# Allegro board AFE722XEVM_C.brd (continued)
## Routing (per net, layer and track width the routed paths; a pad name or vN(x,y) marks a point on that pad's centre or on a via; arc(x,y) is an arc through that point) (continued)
ADCA_DATA_0N: length 48.7
  TOP w0.152: v1(84.79,10.85) 84.75,10.81 84.75,9.53 J14.44 ; v1(50.07,34.82) 50.06,34.82 48.69,36.19 U1.54
  BOTTOM w0.152: v1(50.07,34.82) 50.29,34.61 50.29,34.57 50.57,34.29 50.84,34.29 63.46,21.67 74.19,21.67 83.87,11.99 83.87,11.18 84.15,10.9 84.73,10.9 v1(84.79,10.85)
ADCA_DATA_0P: length 48.7
  TOP w0.152: U1.55 48.88,36.4 49.87,35.41 49.88,35.41 50.01,35.28 50.26,35.28 50.53,35.01 50.53,35 50.76,34.77 v1(50.77,34.77) ; J14.46 84.43,9.53 84.43,10.49 84.33,10.59 84.33,11.33 v1(84.35,11.38)
  BOTTOM w0.152: v1(50.77,34.77) 50.77,34.75 63.58,21.95 74.31,21.95 83.11,13.15 83.3,13.15 83.34,13.19 83.53,13.19 83.66,13.06 83.66,12.87 83.62,12.83 83.62,12.64 84.15,12.1 84.15,11.57 84.34,11.38 v1(84.35,11.38)
ADCA_DATA_1N: length 48.7
  TOP w0.152: v1(48.49,34.8) 48.49,34.96 47.96,35.49 U1.52 ; v1(83.21,10.87) 83.21,10.26 83.22,10.25 83.22,9.56 J14.50
  BOTTOM w0.152: v1(83.21,10.87) 83.16,10.92 82.58,10.92 82.3,11.2 82.3,11.66 73.99,19.96 69.78,19.96 69.47,20.28 69.47,20.4 69.31,20.55 68.7,20.55 68.55,20.4 68.55,20.28 68.24,19.96 67.39,19.96 67.08,20.28 67.08,20.4 66.93,20.55 66.32,20.55 66.16,20.4 66.16,20.28 65.85,19.96 63.42,19.96 49,34.39 48.97,34.39 48.57,34.8 v1(48.49,34.8)
ADCA_DATA_1P: length 48.7
  TOP w0.152: U1.53 48.17,35.67 48.59,35.26 48.68,35.26 48.97,34.97 v1(49.17,34.87) ; v1(82.78,11.4) 82.78,11.09 82.75,11.06 82.75,10.68 82.81,10.63 82.81,10.6 82.93,10.48 82.93,9.53 J14.52
  BOTTOM w0.152: v1(49.17,34.87) 49.17,34.63 49.18,34.63 49.18,34.61 63.54,20.24 65.73,20.24 65.88,20.4 65.88,20.51 66.2,20.83 67.04,20.83 67.36,20.51 67.36,20.4 67.51,20.24 68.12,20.24 68.27,20.4 68.27,20.51 68.59,20.83 69.43,20.83 69.75,20.51 69.75,20.4 69.9,20.24 74.11,20.24 81.77,12.58 81.96,12.58 81.98,12.6 82.16,12.6 82.3,12.47 82.3,12.28 82.28,12.26 82.28,12.07 82.6,11.75 82.6,11.59 82.78,11.42 v1(82.78,11.4)
ADCB_DATA_0N: length 48.7
  TOP w0.152: v1(73.19,11.29) 73.25,11.2 73.25,9.53 J14.70 ; U1.44 44.28,35.69 43.52,34.92 43.42,34.92 43,34.5 v1(43,34.19)
  BOTTOM w0.152: v1(43,34.19) 43,34.16 42.9,34.06 42.9,32.07 45.39,29.58 45.84,29.58 45.95,29.69 46.16,29.69 46.49,29.37 46.49,29.15 46.37,29.04 46.37,28.59 46.86,28.1 47.31,28.1 47.42,28.22 47.64,28.22 47.96,27.89 47.96,27.68 47.85,27.57 47.85,27.12 48.34,26.63 48.78,26.63 48.9,26.74 49.11,26.74 49.44,26.42 49.44,26.2 49.32,26.09 49.32,25.64 49.81,25.16 50.26,25.16 50.37,25.27 50.59,25.27 50.91,24.95 50.91,24.73 50.8,24.62 50.8,24.17 51.28,23.68 51.73,23.68 51.84,23.8 52.06,23.8 52.38,23.47 52.38,23.06 61.62,13.82 70.59,13.82 72.24,12.17 72.24,11.56 72.52,11.28 72.92,11.28 72.93,11.29 v1(73.19,11.29)
ADCB_DATA_0P: length 48.7
  TOP w0.152: J14.72 72.92,9.51 72.92,10.91 72.74,11.1 72.74,11.74 v1(72.72,11.76) ; U1.45 44.48,35.49 43.61,34.62 v1(43.61,34.47)
  BOTTOM w0.152: v1(43.61,34.47) 43.48,34.34 43.48,33.99 43.43,33.93 43.43,33.93 43.18,33.68 43.18,33.37 43.31,33.24 43.38,33.24 43.51,33.11 43.51,32.92 43.38,32.78 43.31,32.78 43.18,32.65 43.18,32.18 43.45,31.91 43.64,31.91 43.66,31.92 43.85,31.92 43.98,31.79 43.98,31.6 43.97,31.58 43.97,31.39 45.5,29.86 45.72,29.86 45.83,29.97 46.28,29.97 46.77,29.48 46.77,29.04 46.65,28.92 46.65,28.71 46.98,28.38 47.19,28.38 47.31,28.5 47.75,28.5 48.24,28.01 48.24,27.56 48.13,27.45 48.13,27.23 48.45,26.91 48.67,26.91 48.78,27.02 49.23,27.02 49.71,26.54 49.71,26.09 49.6,25.98 49.6,25.76 49.93,25.44 50.14,25.44 50.25,25.55 50.7,25.55 51.19,25.06 51.19,24.62 51.08,24.5 51.08,24.29 51.4,23.96 51.61,23.96 51.73,24.08 52.18,24.08 52.66,23.59 52.66,23.17 61.74,14.1 70.7,14.1 71.63,13.17 71.82,13.17 71.85,13.2 72.04,13.2 72.18,13.07 72.18,12.88 72.15,12.84 72.15,12.65 72.52,12.28 72.52,11.96 v1(72.72,11.76)
ADCB_DATA_1N: length 48.7
  TOP w0.152: J14.76 71.72,9.56 71.72,11.2 v1(71.73,11.2) ; v1(41.81,34.34) 41.81,34.61 42.18,34.97 42.18,34.99 43.03,35.84 43.03,35.85 43.57,36.4 43.57,36.47 43.58,36.48 U1.42
  BOTTOM w0.152: v1(71.73,11.2) 71.65,11.28 71.12,11.28 70.84,11.56 70.84,11.57 70.42,11.99 67.49,11.99 66.78,12.7 66.41,12.7 66.26,12.55 66.26,12.3 65.94,11.99 65.25,11.99 64.94,12.3 64.94,12.55 64.78,12.7 64.33,12.7 64.17,12.55 64.17,12.3 63.86,11.99 63.17,11.99 62.85,12.3 62.85,12.55 62.7,12.7 62.24,12.7 62.09,12.55 62.09,12.3 61.78,11.99 60.93,11.99 41.71,31.22 41.71,34.24 v1(41.81,34.34)
ADCB_DATA_1P: length 48.7
  TOP w0.152: J14.78 71.34,9.44 71.45,9.54 71.45,10.84 71.27,11.01 71.27,11.39 71.32,11.44 v1(71.32,11.76) ; U1.43 43.8,36.19 43.78,36.17 43.74,36.17 43.31,35.74 43.31,35.73 42.49,34.91 42.49,34.78 42.44,34.73 v1(42.44,34.59)
  BOTTOM w0.152: v1(42.44,34.59) 42.29,34.44 42.29,34.14 41.99,33.84 41.99,33.5 42.12,33.37 42.13,33.37 42.27,33.23 42.27,33.04 42.13,32.91 42.12,32.91 41.99,32.78 41.99,31.33 61.05,12.27 61.66,12.27 61.81,12.42 61.81,12.66 62.13,12.98 62.82,12.98 63.13,12.66 63.13,12.42 63.29,12.27 63.74,12.27 63.89,12.42 63.89,12.66 64.21,12.98 64.9,12.98 65.22,12.66 65.22,12.42 65.37,12.27 65.83,12.27 65.98,12.42 65.98,12.66 66.29,12.98 66.89,12.98 67.6,12.27 69.51,12.27 69.64,12.4 69.64,12.46 69.77,12.6 69.96,12.6 70.1,12.46 70.1,12.4 70.23,12.27 70.54,12.27 70.99,11.81 71.27,11.81 v1(71.32,11.76)
ADCDATA6: length 48.7
  TOP w0.152: J14.84 69.84,16.09 v1(69.09,16.84) ; U1.48 45.71,34.43 v1(46.08,34.06)
  BOTTOM w0.152: v1(46.08,34.06) 46.08,33.78 48.09,31.76 48.31,31.76 48.53,31.98 48.74,31.98 49.06,31.66 49.06,31.44 48.85,31.22 48.85,31.01 49.17,30.69 49.39,30.69 49.6,30.9 49.82,30.9 50.14,30.58 50.14,30.36 49.93,30.15 49.93,29.93 50.25,29.61 50.47,29.61 50.68,29.82 50.9,29.82 51.22,29.5 51.22,29.29 51,29.07 51,28.85 51.33,28.53 51.54,28.53 51.76,28.75 51.98,28.75 52.3,28.42 52.3,28.21 52.08,27.99 52.08,27.78 52.41,27.45 52.62,27.45 52.84,27.67 53.05,27.67 53.38,27.34 53.38,27.13 53.16,26.91 53.16,26.7 53.48,26.37 53.7,26.37 53.92,26.59 54.13,26.59 54.45,26.27 54.45,26.05 54.24,25.83 54.24,25.62 54.56,25.3 54.78,25.3 54.99,25.51 55.21,25.51 55.53,25.19 55.53,24.97 55.32,24.76 55.32,24.54 55.64,24.22 55.86,24.22 56.07,24.43 56.29,24.43 56.61,24.11 56.61,23.9 56.39,23.68 56.39,23.46 56.72,23.14 56.93,23.14 57.15,23.36 57.36,23.36 57.69,23.03 57.69,22.82 57.47,22.6 57.47,22.39 57.8,22.06 58.01,22.06 58.23,22.28 58.44,22.28 58.77,21.95 58.77,21.74 58.55,21.52 58.55,21.31 58.87,20.98 59.09,20.98 59.31,21.2 59.52,21.2 59.84,20.88 59.84,20.66 59.63,20.44 59.63,20.23 59.95,19.91 60.17,19.91 60.38,20.12 60.6,20.12 60.92,19.8 60.92,19.01 62.69,17.25 68.68,17.25 v1(69.09,16.84)
AUX_SEL: length 45.3
  TOP w0.152: U2.18 90.8,60.66 91.69,59.77 93.27,59.77 94.44,58.6 122.45,58.6 127.84,63.98 127.84,66.5 JP7.2
AUXADC-A: length 23.5
  TOP w0.152: R18.2 36.56,49.55 21.41,64.69 JP15.1
AUXADC-B: length 25.9
  TOP w0.152: R19.2 35.82,49.39 20.73,64.49 19.89,64.49 JP16.1
AUXADC_A: length 8.3
  TOP w0.152: U1.23 43.48,43.97 39.34,48.11 37.92,48.11 R18.1
AUXADC_B: length 8.5
  TOP w0.152: U1.24 43.22,43.67 39.92,46.98 39.33,46.98 38.66,47.65 36.88,47.65 R19.1
AUXDAC-A: length 19.2
  TOP w0.152: R16.2 38.72,51.68 28.7,61.7 JP2.1
AUXDAC-B: length 21.9
  TOP w0.152: JP3.1 25.02,62 36.79,50.23 R17.2
AUXDAC_A: length 8.3
  TOP w0.152: R16.1 40.22,50.23 R52.1 40.28,50.16 40.28,49.61 43.36,46.53 43.36,45.9 43.88,45.37 44.13,45.37 44.47,45.03 U1.20
AUXDAC_B: length 8.5
  TOP w0.152: R17.1 38.02,49.5 R63.1 40.43,48.78 42.9,46.3 42.9,45.92 44.15,44.68 U1.21
CDC_PWRDWN: length 5.6
  TOP w0.152: U2.17 90.44,60.33 90.7,60.07 v1(90.7,59.59)
  BOTTOM w0.152: R110.1 C89.1 92.57,58.03 R111.2 91.49,59.13 91.16,59.13 v1(90.7,59.59)
CDC_REF: length 1
  TOP w0.305: C57.1 R75.1
CDC_REFIN: length 5.3
  TOP w0.254: 82.8,71.1 82.82,71.07 R85.1
  TOP w0.305: R85.1 83.49,70.34 R90.2 84.13,69.75 84.6,69.75 84.94,69.41 84.94,69.39 85.84,68.49 U2.59 ; C57.2 82.8,71.05 82.8,71.1
CDC_RESET: length 7.4
  TOP w0.152: v1(100.08,66.83) 99.97,66.93 95.95,66.93 U2.33
  BOTTOM w0.152: R109.1 R106.1 ; R109.1 100.68,67.24 C75.1 ; R109.1 100.49,67.24 v1(100.08,66.83)
CDC_SEC_REF: length 26
  TOP w0.305: C177.2 R166.2 R167.2 71.54,85.18 71.54,79.49 82.75,68.28 83.99,68.28 84.3,67.96 84.3,67.92 U2.62
CLKIN: length 7.4
  TOP w0.305: R112.2 65.58,64.27 J18.1
CLKINN: length 7.3
  TOP w0.152: R88.2 53.58,47.41 49.59,43.42 U1.8
  TOP w0.305: C55.2 54.04,47.41 R88.2
CLKINP: length 7.3
  TOP w0.152: U1.9 49.36,43.62 53.27,47.53 R88.1
  TOP w0.305: R88.1 53.28,48.12 C51.2
CLOCK_IN: length 2.1
  TOP w0.305: R112.1 R77.1 63.36,60.47 R74.2
CLOCKIN: length 11.5
  TOP w0.305: J9.1 78.51,75.34 R75.2
CP_OUT: length 32.5
  TOP w0.305: U2.3 84.79,64.95 84.35,64.52 v1(83.16,64.52) ; v1(95.71,86.39) 95.71,86.69 R70.2 95.17,87.02 94.82,86.66 C49.2 R71.2
  BOTTOM w0.305: v1(83.16,64.52) 83.11,64.52 82.6,65.02 82.6,69.65 85.98,73.03 85.98,76 95.71,85.73 v1(95.71,86.39)
DAC_DCLK_INN: length 25.9
  TOP w0.152: R95.2 21.82,41.72 21.82,40.97 22.3,40.49 23.06,40.49 23.72,41.15 23.72,42.51 24.22,43 26.14,43 28.35,40.79 32.44,40.79 36.42,36.8 37.74,36.8 38.39,37.45 R62.2 38.56,37.52 38.56,37.7 38.94,38.09 39.31,38.09 39.97,38.75 40.12,38.75 40.75,39.38
DAC_DCLK_INP: length 25.5
  TOP w0.152: U1.33 39.77,39.1 39.77,39.1 39.77,38.95 39.19,38.37 38.82,38.37 38.37,37.92 38.09,37.92 R62.1 38.05,37.87 38.05,37.5 37.63,37.08 36.54,37.08 32.55,41.07 28.46,41.07 26.25,43.28 24.1,43.28 23.44,42.62 23.44,41.26 22.95,40.77 22.42,40.77 22.1,41.09 22.1,41.45 22.69,42.04 R64.1
DAC_FCLK_INN: length 52
  TOP w0.152: 40.75,41.14 40.75,41.29 40.48,41.56 40.47,41.56 39.59,42.43 39.28,42.43 38.83,42.89 R65.2 38.6,43.12 37.42,44.3 29.2,44.3 26.14,47.36 25.92,47.36 25.37,46.81 24.92,46.81 24.33,47.4 24.33,47.85 24.88,48.4 24.88,48.62 24.45,49.05 24.23,49.05 23.68,48.5 23.23,48.5 22.64,49.09 22.64,49.54 23.19,50.09 23.19,50.3 22.76,50.74 22.54,50.74 21.99,50.19 21.54,50.19 20.95,50.78 20.95,51.23 21.5,51.78 21.5,51.99 21.07,52.43 20.85,52.43 20.3,51.87 19.86,51.87 19.26,52.47 19.26,52.92 19.81,53.47 19.81,53.68 19.38,54.11 19.16,54.11 18.61,53.56 18.17,53.56 17.57,54.16 17.57,54.61 18.12,55.16 18.12,55.37 16.9,56.59 6.81,56.59 v1(6.71,56.49)
  BOTTOM w0.152: J15.93 5.27,56.49 v1(6.71,56.49)
DAC_FCLK_INP: length 52.3
  TOP w0.152: U1.30 40.93,41.5 40.59,41.84 40.58,41.84 39.71,42.71 39.4,42.71 39.03,43.09 R65.1 38.79,43.32 37.54,44.58 29.31,44.58 26.25,47.64 25.8,47.64 25.25,47.09 25.04,47.09 24.61,47.52 24.61,47.73 25.16,48.28 25.16,48.73 24.56,49.33 24.12,49.33 23.56,48.78 23.35,48.78 22.92,49.21 22.92,49.42 23.47,49.97 23.47,50.42 22.87,51.02 22.43,51.02 21.88,50.46 21.66,50.46 21.23,50.9 21.23,51.11 21.78,51.66 21.78,52.11 21.18,52.7 20.74,52.7 20.19,52.15 19.97,52.15 19.54,52.59 19.54,52.8 20.09,53.35 20.09,53.8 19.5,54.39 19.05,54.39 18.5,53.84 18.28,53.84 17.85,54.27 17.85,54.49 18.4,55.04 18.4,55.49 17.02,56.87 6.97,56.87 6.9,56.95 6.35,56.95 6.3,56.99 v1(6.22,56.99)
  BOTTOM w0.152: v1(6.22,56.99) 6.05,56.82 5.24,56.82 J15.91
DACA_DATA_0N: length 52
  TOP w0.152: 41.46,41.85 41.46,42.02 41.11,42.36 41.1,42.36 40.25,43.21 40.25,43.22 39.74,43.74 39.52,43.74 R66.2 39.48,44.01 38.21,45.29 31.47,45.29 27.57,49.19 27.35,49.19 26.96,48.8 26.51,48.8 25.92,49.4 25.92,49.84 26.31,50.24 26.31,50.45 25.88,50.88 25.66,50.88 25.27,50.49 24.82,50.49 24.23,51.08 24.23,51.53 24.62,51.92 24.62,52.14 24.19,52.57 23.97,52.57 23.58,52.18 23.13,52.18 22.54,52.77 22.54,53.22 22.93,53.61 22.93,53.83 22.5,54.26 22.28,54.26 21.89,53.87 21.44,53.87 20.85,54.46 20.85,54.91 21.24,55.3 21.24,55.52 20.81,55.95 20.59,55.95 20.2,55.56 19.75,55.56 19.16,56.15 19.16,56.6 19.55,56.99 19.55,57.21 15.77,60.99 v1(6.65,60.99)
  BOTTOM w0.152: v1(6.65,60.99) 5.26,60.99 J15.75
DACA_DATA_0P: length 52.4
  TOP w0.152: U1.28 41.66,42.2 41.23,42.64 41.22,42.64 40.53,43.33 40.53,43.34 39.92,43.95 R66.1 39.68,44.21 38.32,45.57 31.59,45.57 27.68,49.47 27.23,49.47 26.84,49.08 26.63,49.08 26.2,49.51 26.2,49.73 26.59,50.12 26.59,50.57 25.99,51.16 25.55,51.16 25.15,50.77 24.94,50.77 24.51,51.2 24.51,51.42 24.9,51.81 24.9,52.26 24.3,52.85 23.86,52.85 23.46,52.46 23.25,52.46 22.82,52.89 22.82,53.1 23.21,53.5 23.21,53.94 22.61,54.54 22.17,54.54 21.77,54.15 21.56,54.15 21.13,54.58 21.13,54.79 21.52,55.19 21.52,55.63 20.93,56.23 20.48,56.23 20.09,55.84 19.87,55.84 19.44,56.27 19.44,56.48 19.83,56.88 19.83,57.32 15.89,61.26 7.02,61.26 6.84,61.44 6.27,61.44 v1(6.22,61.49)
  BOTTOM w0.152: J15.73 5.25,61.32 6.05,61.32 v1(6.22,61.49)
DACA_DATA_1N: length 52
  TOP w0.152: v1(6.71,62.48) 6.72,62.5 17.77,62.5 20.92,59.35 20.92,59.13 20.49,58.7 20.49,58.25 21.08,57.66 21.53,57.66 21.96,58.09 22.18,58.09 22.61,57.66 22.61,57.44 22.18,57.01 22.18,56.56 22.77,55.97 23.22,55.97 23.65,56.4 23.86,56.4 24.3,55.97 24.3,55.75 23.87,55.32 23.87,54.87 24.46,54.28 24.91,54.28 25.34,54.71 25.55,54.71 25.99,54.28 25.99,54.06 25.55,53.63 25.55,53.19 26.15,52.59 26.6,52.59 26.89,52.88 27.38,52.88 33.66,46.61 38.64,46.61 40.35,44.9 R67.2 40.39,44.63 40.56,44.63 41.04,44.16 41.04,43.85 42.16,42.72 U1.27
  BOTTOM w0.152: J15.69 5.29,62.52 6.07,62.52 6.07,62.51 6.68,62.51 v1(6.71,62.48)
DACA_DATA_1P: length 52.4
  TOP w0.152: U1.26 42.38,42.91 41.84,43.45 41.83,43.45 41.31,43.97 41.31,44.27 40.78,44.81 R67.1 40.55,45.1 38.75,46.89 33.77,46.89 27.5,53.16 26.77,53.16 26.48,52.87 26.27,52.87 25.83,53.3 25.83,53.52 26.26,53.95 26.26,54.39 25.67,54.99 25.22,54.99 24.79,54.56 24.58,54.56 24.14,54.99 24.14,55.21 24.58,55.64 24.58,56.08 23.98,56.68 23.53,56.68 23.1,56.25 22.89,56.25 22.46,56.68 22.46,56.89 22.89,57.33 22.89,57.77 22.29,58.37 21.84,58.37 21.41,57.94 21.2,57.94 20.77,58.37 20.77,58.58 21.2,59.01 21.2,59.46 17.88,62.78 7.06,62.78 6.9,62.94 6.38,62.94 6.32,62.99 v1(6.27,62.99)
  BOTTOM w0.152: v1(6.27,62.99) 6.08,62.8 5.27,62.8 J15.67
DACB_DATA_0N: length 52.3
  TOP w0.152: 41.46,38.67 41.29,38.67 40.94,38.33 40.94,38.33 39.38,36.77 R60.2 39.15,36.56 38.25,35.66 36.6,35.66 36.47,35.79 36.26,35.79 35.83,36.22 v1(35.79,36.22)
  BOTTOM w0.152: J15.81 5.83,59.4 5.94,59.51 6.79,59.51 7.32,58.98 7.32,57.86 7.8,57.38 8.8,57.38 9.8,56.37 9.8,49.66 10.64,48.82 22.68,48.82 34.78,36.73 35.54,36.73 35.79,36.47 v1(35.79,36.22)
DACB_DATA_0P: length 52
  TOP w0.152: U1.35 41.1,38.88 39.22,36.99 R60.1 38.95,36.76 38.13,35.94 36.72,35.94 36.45,36.21 v1(36.45,36.25)
  BOTTOM w0.152: v1(36.45,36.25) 36.45,36.25 35.99,36.7 35.96,36.7 35.65,37 34.89,37 22.8,49.1 10.76,49.1 10.08,49.77 10.08,56.49 8.92,57.66 7.91,57.66 7.59,57.98 7.59,59.09 6.9,59.79 5.94,59.79 5.83,59.9 J15.79
DACB_DATA_1N: length 52.3
  TOP w0.152: v1(34.01,35.13) 34.1,35.13 34.51,34.72 34.68,34.72 34.81,34.59 38.91,34.59 40.02,35.7 R55.2 40.25,35.91 40.54,36.21 40.54,36.51 41.99,37.96 U1.38
  BOTTOM w0.152: v1(34.01,35.13) 21.52,47.62 10.59,47.62 9.02,49.2 9.02,50.15 8.27,50.9 7.7,50.9 7.24,51.36 7.24,56.98 6.21,58.01 5.89,58.01 5.77,57.89 J15.87
DACB_DATA_1P: length 52.1
  TOP w0.152: U1.37 41.81,38.17 40.26,36.62 40.26,36.32 40.07,36.13 R55.1 39.81,35.89 38.79,34.87 34.92,34.87 34.7,35.1 v1(34.7,35.18)
  BOTTOM w0.152: J15.85 5.84,58.39 5.94,58.29 6.32,58.29 7.52,57.1 7.52,51.47 7.81,51.18 8.38,51.18 9.3,50.27 9.3,49.32 10.71,47.9 21.63,47.9 33.93,35.61 34.26,35.61 v1(34.7,35.18)
DACCLK_IN: length 8.7
  TOP w0.305: J21.1 24.77,32.27 T6.3
FPGA_CLKN: length 82.8
  TOP w0.152: R149.2 86.32,58.8 86.84,58.8 87.15,59.11 87.15,60.77 87.58,61.2 87.58,61.24 87.97,61.63 U2.12 ; R151.1 85.56,57.89 85.12,57.44 85.12,57.28 v1(84.91,57.07)
  TOP w0.305: R149.2 86.27,58.76 85.56,58.05 R151.1
  BOTTOM w0.152: J15.118 12.01,50.39 12.13,50.51 33.79,50.51 40.59,57.3 84.68,57.3 v1(84.91,57.07)
FPGA_CLKP: length 83
  TOP w0.152: v1(85.57,57.25) 85.62,57.3 86.26,57.3 R150.1 ; U2.13 88.22,61.42 87.86,61.06 87.83,61.06 87.43,60.66 87.43,58.99 87,58.56 R148.2
  TOP w0.305: R150.1 R148.2
  BOTTOM w0.152: v1(85.57,57.25) 85.42,57.25 85.11,57.56 84.82,57.56 84.8,57.58 40.47,57.58 33.68,50.79 12.12,50.79 12.01,50.89 J15.116
FPGA_SCLK: length 31.8
  TOP w0.152: J14.115 61.84,4.97 61.42,5.38 61.42,6.96 60.9,7.48 60.24,7.48 58.88,8.83 58.88,18.85 64.49,24.46 64.49,29.75 63.5,30.73 R3.2
FPGA_SDATA: length 32.9
  TOP w0.152: R8.2 64.03,29.18 64.03,24.76 56.44,17.17 56.44,7.49 58.22,5.71 60.07,5.71 61.34,4.45 J14.117
FPGA_SDO: length 33
  TOP w0.152: R51.2 64.16,31.09 64.16,30.94 64.97,30.12 64.97,24.23 59.39,18.64 59.39,9.02 60.43,7.98 61.11,7.98 61.93,7.16 61.93,5.59 62.34,5.18 J14.113
FPGA_SEN: length 31.7
  TOP w0.152: R10.2 63.5,24.94 55.94,17.38 55.94,7.23 57.84,5.33 59.74,5.33 60.84,4.24 J14.119
IN1: length 37.3
  TOP w0.152: R125.1 45.97,66.65 45.47,67.16 44.5,67.16 44.22,67.44 44.22,89.52 41,92.75 41,95.43 41.83,96.27 42.51,96.27 42.8,95.97 C95.2 ; U3.22 44.06,96.15 R155.2
  TOP w0.305: R155.2 C95.2
INA+: length 28.5
  TOP w0.305: R36.1 124.69,48.64 132.59,56.54 J3.1
INA-: length 28.5
  TOP w0.305: J4.1 131.32,46.38 127.91,42.98 124.78,42.98 123.53,44.22 122.92,44.22 121.6,42.9 120.99,42.9 119.75,44.15 118.99,44.15 118.4,43.56 R42.2
INB+: length 28.5
  TOP w0.305: R22.1 118.22,33.02 118.71,32.54 119.47,32.54 120.43,33.5 121.2,33.5 122.16,32.54 122.92,32.54 123.89,33.5 124.65,33.5 125.51,32.64 127.3,32.64 130.89,36.22 J1.1
INB-: length 28.5
  TOP w0.305: R29.2 119.1,27.81 119.76,28.47 120.53,28.47 121.85,27.15 122.61,27.15 123.93,28.47 124.69,28.47 125.94,27.23 126.85,27.23 128.1,28.47 129.95,28.47 132.36,26.06 J2.1
IOUT-N-A: length 28.7
  TOP w0.305: R57.2 51.85,72 51.85,89.11 57.35,94.62 J6.1
IOUT-N-B: length 28.7
  TOP w0.305: J8.1 30.78,94.62 29.18,93.01 29.18,77.06 34.52,71.73 R69.2
IOUT-P-A: length 20.6
  TOP w0.305: J5.1 60.96,87.5 59.46,89 57.28,89 55.91,87.63 55.91,80.21 58.22,77.9 58.42,77.9 T5.1
IOUT-P-B: length 20.7
  TOP w0.305: J7.1 33.66,87.76 34.82,88.93 37.36,88.93 38.89,87.4 38.89,79.65 41,77.54 T7.1
IOUTN-A: length 19.9
  TOP w0.305: R56.1 48.64,57.45 49.1,57.91 52.58,57.91 53.34,58.67 R13.2 53.34,71.85 T5.4
IOUTN-B: length 19.9
  TOP w0.305: T7.4 35.92,68.73 R54.2 35.94,60.27 40.26,55.96 R68.1
IOUTN_A: length 13.5
  TOP w0.152: R56.2 49.76,55.96 50.22,55.5 50.22,52.27 49.12,51.18 49.12,46.29 48.72,45.88 48.72,45.82 47.93,45.03 U1.13
  TOP w0.305: R56.2 49.66,56.97 R133.2
IOUTN_B: length 13.4
  TOP w0.152: U1.16 46.86,46.09 47.32,46.55 47.32,50.32 46.74,50.9 45.8,50.9 45.14,51.56 45.14,52.15 44.27,53.01 44.27,55.47 43.79,55.96 R68.2
  TOP w0.305: R68.2 43.69,56.95 R114.2
IOUTP-A: length 20.4
  TOP w0.305: R47.1 58.42,71.48 R12.2 58.42,60.07 54.31,55.96 51.69,55.96
IOUTP-B: length 19.6
  TOP w0.305: T7.6 41,68.73 R53.2 41.02,58.8 41.91,57.91 45.2,57.91 45.72,57.39 R58.1
IOUTP_A: length 13.5
  TOP w0.152: U1.12 48.17,44.85 49.02,45.7 49.02,45.76 49.43,46.16 49.43,51.05 50.52,52.15 50.52,55.8 R46.2
  TOP w0.305: R46.2 50.67,56.95 50.8,57.07 R127.2
IOUTP_B: length 13.5
  TOP w0.152: R58.2 44.58,55.83 44.58,53.14 45.44,52.27 45.44,51.69 45.92,51.21 46.86,51.21 47.62,50.44 47.62,46.41 47.11,45.9 U1.15
  TOP w0.305: R120.2 44.7,56.95 R58.2
IP1: length 37.4
  TOP w0.152: R117.1 42.42,66.4 43.21,67.18 43.66,67.18 43.94,67.46 43.94,89.41 40.72,92.63 40.72,95.55 41.71,96.55 42.42,96.55 C96.2 ; U3.21 44.09,96.65 R155.1
  TOP w0.305: R155.1 C96.2
MODE_SEL: length 50.8
  TOP w0.152: JP5.2 131.32,66.55 131.32,64.34 124.43,57.45 92.13,57.45 89.38,60.2 U2.16
OUT: length 5.3
  TOP w0.305: C58.1 87.86,89.4 VCXO1.4
OUTB: length 5.3
  TOP w0.305: C54.1 90.4,89.5 VCXO1.5
PDN: length 50.5
  TOP w0.152: v1(49.86,36.27) 49.23,36.9 U1.56
  BOTTOM w0.152: JP1.2 92.74,25.7 63.3,25.7 54.53,34.47 53.16,34.47 51.36,36.27 v1(49.86,36.27)
PLL_LOCK: length 9.5
  TOP w0.152: R91.2 90.45,79.3 87.6,76.45 87.6,73.18 89.03,71.75 U2.50
PLLLOCK: length 1
  TOP w0.152: R91.1 R92.2
PWRDWN: length 38.8
  TOP w0.152: JP8.1 124.82,66.4 124.82,64.16 119.86,59.21 v1(96.22,59.21)
  BOTTOM w0.152: R111.1 94.34,57.34 v1(96.22,59.21)
QN1: length 37.2
  TOP w0.152: C108.2 52.7,96.29 53.14,96.29 53.59,95.83 53.59,93.05 50.04,89.5 50.04,67.46 49.78,67.21 48.97,67.21 48.39,66.62 R140.1 ; U3.9 49.63,96.24 50.88,96.24 R154.2
  TOP w0.305: R154.2 52.27,95.86 C108.2
QP1: length 37.4
  TOP w0.152: C109.2 52.59,96.57 53.25,96.57 53.87,95.95 53.87,92.94 50.32,89.38 50.32,67.44 50.57,67.18 51.13,67.18 51.94,66.37 R130.1 ; U3.10 49.62,96.57 50.95,96.57 R154.1
  TOP w0.305: R154.1 52.27,96.88 C109.2
REF_SEL: length 2
  TOP w0.152: v1(91.34,72.62) 91.34,72.24 90.8,71.7 U2.47
  BOTTOM w0.152: R101.1 91.06,72.92 91.34,72.64 v1(91.34,72.62)
RF_LO_IN: length 31.3
  TOP w0.305: v1(48.06,89.89) 47.76,89.89 arc(47.54,89.93) 47.36,90.06 arc(47.24,90.24) 47.19,90.45 C103.1
  BOTTOM w0.305: 59.97,113.67 59.97,104.96 arc(59.78,103.99) 59.23,103.17 52.56,96.5 arc(52.01,95.68) 51.82,94.71 51.82,92.34 arc(51.63,91.41) 51.1,90.63 arc(50.32,90.1) 49.39,89.92 48.08,89.92 v1(48.06,89.89)
RFOUT: length 12.3
  TOP w0.305: C106.2 47.27,113.67
RST: length 24.8
  BOTTOM w0.152: R109.2 101.23,67.78 102.41,66.6 117.65,66.6 JP6.1 119,68.02 122.68,71.7 SW2.1
SCLK: length 15.9
  TOP w0.152: R3.1 v1(61.85,30.73) 57.37,30.73 53.11,34.99 53.11,35.14 U1.59
  BOTTOM w0.152: R3.1 v1(61.85,30.73)
SDATA: length 16.5
  TOP w0.152: R8.1 v1(61.85,29.72) 57.78,29.72 49.94,37.56 U1.58
  BOTTOM w0.152: v1(61.85,29.72) R8.1
SDO: length 15.2
  TOP w0.152: U1.60 50.65,38.28 52.73,36.2 53.21,36.2 57.66,31.75 v1(61.85,31.75) R51.1
  BOTTOM w0.152: v1(61.85,31.75) R51.1
SEN: length 17.1
  TOP w0.152: R10.1 v1(61.85,28.7) 58.04,28.7 50.32,36.42 50.32,36.46 49.59,37.19 U1.57
  BOTTOM w0.152: R10.1 v1(61.85,28.7)
SPI_CLK: length 81.5
  TOP w0.152: J20.4 110.01,21.87 110.01,9.02 110.46,8.56 v1(110.46,8.51) ; v1(93.17,75.82) 92.73,75.38 R104.2 92.73,75.32 R100.1 92.01,74.35 91.85,74.18 91.85,72.02 U2.46
  BOTTOM w0.152: J20.4 111.28,53.44 93.18,71.54 93.18,75.81 v1(93.17,75.82) ; R159.1 v1(110.46,8.51)
SPI_LE: length 91.6
  TOP w0.152: v1(94.62,74.37) 94.17,73.92 R103.2 R99.1 93.45,72.98 91.5,71.03 U2.45 ; v1(110.59,3.43) 109.96,3.43 107.47,5.92 107.47,21.87 J20.2
  BOTTOM w0.152: v1(94.62,74.37) 94.62,75.49 93.68,76.43 93.09,76.43 91.85,75.18 91.85,71.12 96.8,66.17 97.21,66.17 109.17,54.2 109.17,23.57 J20.2 ; R136.1 v1(110.59,3.43)
SPI_MISO: length 77.7
  TOP w0.152: v1(88.37,59.13) 88.57,59.33 88.57,60.27 89.01,60.72 U2.15 ; v1(110.54,4.45) 110.54,6.2 115.09,10.74 115.09,21.87 J20.8
  BOTTOM w0.152: J20.8 115.11,21.89 108.1,21.89 106.83,23.16 106.83,38.84 89.03,56.64 89.03,58.47 v1(88.37,59.13) ; R158.1 v1(110.54,4.45)
SPI_MOSI: length 77.9
  TOP w0.152: v1(110.52,9.53) 110.52,10.54 112.55,12.57 112.55,21.87 J20.6 ; U2.44 91.86,70.65 92.61,71.4 94.55,71.4 R98.1 R102.2 95.6,72.46 v1(96.04,72.9)
  BOTTOM w0.152: v1(96.04,72.9) 96.04,70.74 96.98,69.8 96.98,68.96 113.49,52.45 113.49,42.26 113.44,42.21 113.44,41.81 113.49,41.76 113.49,23.47 J20.6 ; R160.1 v1(110.52,9.53)
SYNCINN: length 52.2
  TOP w0.152: v1(41.73,36.09) 41.73,36.3 42.34,36.91 42.42,36.91 42.77,37.25 U1.40
  BOTTOM w0.152: v1(41.73,36.09) 41.5,35.86 41.48,35.86 41.39,35.78 41.24,35.78 38.02,32.56 29.08,32.56 25.04,28.52 23.66,28.52 23.51,28.37 23.51,28.08 23.2,27.76 22.35,27.76 22.04,28.08 22.04,29.13 21.89,29.29 21.28,29.29 21.12,29.13 21.12,28.08 20.81,27.76 19.97,27.76 19.65,28.08 19.65,29.13 19.5,29.29 18.89,29.29 18.74,29.13 18.74,28.08 18.42,27.76 17.58,27.76 17.26,28.08 17.26,29.13 17.11,29.29 16.5,29.29 16.35,29.13 16.35,28.08 16.03,27.76 15.19,27.76 14.88,28.08 14.88,29.13 14.72,29.29 14.11,29.29 13.96,29.13 13.96,28.84 13.65,28.52 10.65,28.52 8.17,31.01 5.94,31.01 5.82,30.89 J15.175
SYNCINP: length 52
  TOP w0.152: v1(41.07,36.27) 41.25,36.27 42.17,37.19 42.19,37.19 42.52,37.51 U1.39
  BOTTOM w0.152: v1(41.07,36.27) 41.07,36.01 37.91,32.84 28.97,32.84 24.93,28.8 23.55,28.8 23.23,28.49 23.23,28.19 23.08,28.04 22.47,28.04 22.32,28.19 22.32,29.25 22,29.57 21.16,29.57 20.85,29.25 20.85,28.19 20.69,28.04 20.08,28.04 19.93,28.19 19.93,29.25 19.61,29.57 18.77,29.57 18.46,29.25 18.46,28.19 18.31,28.04 17.7,28.04 17.54,28.19 17.54,29.25 17.23,29.57 16.39,29.57 16.07,29.25 16.07,28.19 15.92,28.04 15.31,28.04 15.16,28.19 15.16,29.25 14.84,29.57 14,29.57 13.68,29.25 13.68,28.96 13.53,28.8 10.77,28.8 8.29,31.29 5.94,31.29 5.84,31.39 J15.173
TCXO_VCC: length 10.1
  TOP w0.508: R165.2 v1(71.07,101.37) 71.22,101.22 75.93,101.22 U17.8
  BOTTOM w0.508: U16.9 71.07,100.15 v1(71.07,101.37)
USB_SCLK: length 62.7
  BOTTOM w0.152: R137.1 110.46,6.48 103.3,13.64 103.3,20.98 97.14,27.14 97.14,27.14 96.91,27.14 94.03,30.02 87.27,30.02 86.84,30.45 83.04,30.45 82.17,29.59 80.04,29.59 79.68,29.95 79.66,29.95 78.87,30.73 R1.2
USB_SDATA: length 62.5
  BOTTOM w0.152: R138.1 110.57,5.46 102.51,13.51 102.51,21.01 94.03,29.49 87,29.49 86.95,29.44 83.44,29.44 82.93,28.93 76.9,28.93 76.11,29.72 R6.2
USB_SDO: length 64.1
  BOTTOM w0.152: R141.1 110.36,7.49 104.06,13.79 104.06,24.13 97.49,30.71 96.06,30.71 95.83,30.48 87.45,30.48 87.1,30.84 81.61,30.84 81.36,30.58 80.21,30.58 79.04,31.75 R11.2
USB_SEN: length 68.2
  BOTTOM w0.152: R139.1 111.18,10.54 111.63,10.08 111.63,5.14 111.47,4.98 110.21,4.98 101.83,13.36 101.83,21.13 94.46,28.5 63.7,28.5 R9.2
V_CTRL: length 23
  TOP w0.305: C48.2 95.48,88.7 R70.1 95.38,97.33 92.94,99.77 VCXO1.1 99.5,101.69 TP4.1
VBB: length 3.8
  TOP w0.305: U2.56 86.91,69.61 86.49,70.03 86.49,70.15 C85.2 85.54,72.08 R84.1
VCM: length 44.2
  TOP w0.254: R7.1 57.19,35.72 arc(57.26,35.68) 57.34,35.66 TP1.1
  TOP w0.305: C37.2 R27.1 v1(82.68,32.64) R25.2 ; R40.1 v1(82.68,43.84) R38.2 C43.2
  BOTTOM w0.305: v1(82.68,43.84) v1(82.68,32.64) 79.73,32.64 76.71,35.66 TP1.1
VCXO_IN: length 19.3
  TOP w0.152: U2.53 87.97,70.78 87.63,71.12 87.63,71.15 85.88,72.9 85.88,79.22 88.85,82.19 88.85,85.32 R87.1
  TOP w0.305: R87.1 R89.1 88.56,87.68 C58.2
VCXO_INB: length 36.7
  TOP w0.152: U2.52 88.24,70.97 86.18,73.02 86.18,79.1 89.15,82.07 89.15,85.16 R80.1
  TOP w0.305: R84.2 84.8,73.09 v1(84.4,73.48) ; v1(90.12,87.68) C54.2 89.6,86.65 R83.1 89.58,85.62 R80.1
  BOTTOM w0.305: v1(90.12,87.68) 84.4,81.97 v1(84.4,73.48)
Y0: length 5.9
  TOP w0.305: R144.2 67.37,61.22 65.98,59.83 R76.2
Y0P: length 4.5
  TOP w0.305: 86.2,63.54 85.73,63.07 82,63.07 C71.2
Y0P_FLTR: length 6
  TOP w0.305: C71.1 80.51,61.71 C72.2 79.77,60.92 L9.1 79.63,60.63 77.18,58.18 FLT1.1
Y1N: length 29.3
  TOP w0.152: U2.9 86.91,62.7 85.93,61.72 84.45,61.72 83.88,61.14 83.87,61.14 83.54,60.81 83.03,60.81 82.85,60.99 82.71,60.99 R96.1 82.66,60.87 82.58,60.78 82.79,60.57 82.79,60.11 77.01,54.33 73.05,54.33 69.45,57.93 65.28,57.93 64.97,58.24 64.67,58.24 64.47,58.05 64.47,57.83 64.65,57.65 R81.2
Y1P: length 29.3
  TOP w0.152: U2.10 87.1,62.48 86.06,61.44 84.57,61.44 84.15,61.03 84.15,61.01 83.58,60.44 83.58,60.43 R97.1 83.34,60.22 77.16,54.05 72.93,54.05 69.36,57.63 65.52,57.63 64.95,57.06 64.74,57.06 64.13,57.67 R79.2
N27753747: length 1.9
  TOP w0.305: U3.16 47.28,100.32 C106.1
N27753749: length 8.7
  TOP w0.305: U3.18 46.28,98.65 45.97,98.96 43.81,98.96
  TOP w0.508: v1(43.81,99.47) 43.81,98.96
  BOTTOM w0.508: C105.1 43.81,101.28 v1(43.81,99.47) 43.84,99.44 C102.1
  BOTTOM w1.016: C105.1 43.43,101.89 FB5.2
N27753751: length 8.1
  TOP w0.305: U3.24 45.11,95.15 43.81,93.85
  TOP w0.508: 43.81,93.85 v1(43.81,93.34)
  BOTTOM w0.508: C97.1 43.81,91.53 v1(43.81,93.34) 43.81,93.85
  BOTTOM w1.016: FB4.2 43.56,91 C97.1
N27753768: length 1
  TOP w0.305: R124.1 C107.2
N27753778: length 2.6
  TOP w0.305: C107.1 47.78,92.47 U3.4
N27753917: length 2.5
  TOP w0.305: C103.2 47.28,92.03 U3.3
N27836198: length 7.8
  BOTTOM w0.305: v1(122.94,110.49) 122.96,110.51 Q1.4 Q1.7 123.08,109.71 123.06,109.73
  BOTTOM w0.508: 123.06,109.73 123.06,109.6 122.43,108.97 v1(122.43,108.46) ; v1(117.98,108.59) FB7.2 v1(117.09,107.57) ; v1(121.01,107.34) C121.1 v1(119.57,108.37)
  vias: v1(118.62,108.59) v1(121.92,109.47)
N27836250: length 3.4
  BOTTOM w0.305: Q1.1 Q1.2 124.21,109.3 Q1.8 124.21,109.91 Q1.5 Q1.6
N27836254: length 2.1
  TOP w0.508: D2.1 115.29,111.91 v1(115.06,111.91)
  BOTTOM w0.508: R142.1 v1(115.06,111.91)
N28104733: length 4.5
  TOP w0.254: L18.2 128.65,90.83 129.17,91.35 U6.3
  TOP w0.508: C132.1 129.01,88.57 C133.1
N28104810: length 3.1
  TOP w0.254: L18.1 128.65,93.12 128.85,92.91 128.91,92.84 128.98,92.79 129.12,92.65 U6.1
N28106468: length 10.4
  TOP w0.254: U6.5 134.09,92 C130.1 134.61,91.35 U6.4
  TOP w0.762: C130.1 135.31,92.05 138.3,92.05 139.83,93.57 JP11.2
N28122875: length 1.5
  BOTTOM w0.508: U7.5 C135.1
N28122877: length 10.9
  BOTTOM w0.762: U7.4 129.72,88.75 C136.1 129.72,85.78 129.03,85.09 126.87,85.09 125.55,86.41 JP12.3
N28122879: length 13.2
  BOTTOM w0.762: U7.2 132.28,86.46 C151.1 132.99,86.23 133.55,86.79 U7.1 133.83,88.49 138.56,88.49 139.83,89.76 JP19.2
N28166986: length 3.2
  TOP w0.305: R115.1 C90.1 R113.2 43.69,58.78 R114.1
N28167010: length 2.6
  TOP w0.305: C92.1 43.56,66.5 L10.1 42.95,64.9 R117.2
N28167012: length 4.5
  TOP w0.305: L10.2 43.69,63.8 C91.1 ; C91.1 C90.2 R115.2 ; C91.1 R116.1
N28167020: length 2.6
  TOP w0.305: C92.2 44.83,66.5 L12.1 45.44,64.9 R125.2
N28167104: length 3.2
  TOP w0.305: R120.1 44.7,58.78 R118.2 C94.1 R121.1
N28167112: length 4.5
  TOP w0.305: C91.2 44.7,63.8 L12.2 ; C91.2 R122.1 ; C91.2 C94.2 R121.2
N28168729: length 4.5
  TOP w0.305: C111.2 R134.2 C114.2 ; C111.2 R135.1 ; C111.2 49.66,63.83 L16.2
N28168733: length 3.2
  TOP w0.305: R133.1 49.53,59.66 R132.2 R134.1 C114.1
N28168739: length 2.6
  TOP w0.305: C112.1 50.8,66.55 L14.1 51.44,64.9 R130.2
N28168741: length 2.6
  TOP w0.305: R140.2 48.89,64.9 L16.1 49.53,66.55 C112.2
N28287802: length 4.5
  TOP w0.305: C111.1 50.67,63.83 L14.2 ; C111.1 R128.2 C110.2 ; C111.1 R129.1
N28296464: length 3.2
  TOP w0.305: C110.1 R128.1 R126.2 50.8,59.66 R127.1
N29051346: length 2.5
  TOP w0.305: R123.2 46,93.88 46.28,94.16 U3.1
N29488937: length 3.2
  TOP w0.305: R81.1 65.57,55.73 T9.1
N29488984: length 3.4
  TOP w0.305: R74.1 61.74,59.09 T9.3
N29489205: length 5.5
  TOP w0.305: U2.35 95.04,67.46 97.13,69.54 R108.2 97.16,69.62 R105.1 98.05,70.66 C74.2
N29489357: length 1.4
  TOP w0.152: R92.1 92.53,79.3 D1.1
N29489396: length 16.3
  TOP w0.508: 55.96,49.81 R78.2 ; 55.96,49.81 58.32,52.18 58.37,52.18 ; 55.96,49.81 R82.1 ; 58.37,52.18 T9.5 T9.2 62.28,56.08 v1(60.35,54.15) 58.37,52.18
  BOTTOM w0.508: C56.1 v1(60.35,54.15)
N29489542: length 5.3
  TOP w0.305: C55.1 56.88,48.84 R161.2 58.7,48.86 T9.6
N29489733: length 2.2
  TOP w0.305: R73.1 100.28,99.42 JP4.1
N29489951: length 2.1
  TOP w0.508: JP5.1 132.84,71.12 R107.1
N29490085: length 5.3
  TOP w0.305: FLT1.5 72.64,57.26 70.97,58.93 L8.1 70.25,58.93 C73.2 C70.2
N29490446: length 5.1
  TOP w0.305: C51.1 54.73,51 R78.1 54.75,52.09 T9.4
N29490682: length 13.9
  TOP w0.305: VCXO1.2 v1(90.4,98.25)
  BOTTOM w0.305: JP4.2 91.74,96.9 v1(90.4,98.25)
N29639772: length 2.6
  TOP w0.152: v1(44.09,47.22) 44.39,46.92 44.39,46.77 45.34,45.82 U1.18
  BOTTOM w0.152: v1(44.09,47.22) 43.83,47.48 R15.2
N29650049: length 4.4
  TOP w0.152: 51.71,39.38 51.71,39.38 52.37,38.71 52.37,38.7 52.55,38.52 52.55,38.51 53.78,37.28 C1.1 54.9,38.01 R7.2
N29655636: length 3.7
  TOP w0.152: 51,38.67 51,38.66 51.92,37.74 51.92,37.67 v1(52.6,36.98)
  BOTTOM w0.508: R5.1 52.55,36.43 52.55,36.93 v1(52.6,36.98) 52.67,37.05 R2.2
N29813891: length 5.6
  TOP w0.305: R61.1 R59.2
N29813928: length 4.3
  TOP w0.508: T7.5 v1(38.46,74.44)
  BOTTOM w0.508: R50.1 C81.1 37.95,74.44 v1(38.46,74.44)
N29814161: length 5.6
  TOP w0.305: 59.82,77.44 R47.2
N29814197: length 3.9
  TOP w0.508: T5.5 v1(55.88,74.67)
  BOTTOM w0.508: R48.1 55.88,74.65 ; 55.88,74.65 C79.1 ; 55.88,74.65 v1(55.88,74.67)
N29978719: length 3
  BOTTOM w0.152: U4.11 112.41,10.28 R139.2
N29978744: length 13.8
  TOP w0.508: v1(131.83,8.38) 131.83,16.13 v1(132.56,16.87)
  BOTTOM w0.508: J16.1 v1(132.56,16.87) ; FB6.2 129.39,7.39 C116.1 130.84,7.39 v1(131.83,8.38)
N29978873: length 15.5
  TOP w0.152: v1(129.82,12.29) 128.85,11.33 123.79,11.33 v1(123.46,11.65)
  BOTTOM w0.152: v1(129.82,12.29) C119.1 131.83,13.56 131.83,15.37 132.52,16.07 J16.2 ; v1(123.46,11.65) 123.39,11.58 U4.16
N29978893: length 8.4
  BOTTOM w0.381: C117.1 124.73,9.89 123.81,8.98 U4.20
  BOTTOM w0.508: FB6.1 125.86,7.87 C117.1 126.38,10.41 C115.1
N29978897: length 3.1
  BOTTOM w0.152: R136.2 112.49,3.78 U4.1
N29978919: length 16.3
  BOTTOM w0.381: U4.4 116.65,5.73 117.88,6.96 117.88,9.27 119.55,10.94 120.68,10.94 120.69,10.93 U4.17 123.12,10.93 123.13,10.94 123.92,10.94 124.26,11.28 C120.1
N29978933: length 17.4
  TOP w0.152: v1(129.82,11.07) 129.79,11.07 129.51,10.79 123.47,10.79 122.94,11.33 122.94,11.81 v1(123.47,12.34)
  BOTTOM w0.152: v1(123.47,12.34) 123.35,12.23 U4.15 ; v1(129.82,11.07) C118.1 132.33,12.85 132.33,14.86 132.74,15.27 J16.3
N29979080: length 3.1
  BOTTOM w0.152: U4.6 112.61,7.03 R141.2
N29979098: length 3.1
  BOTTOM w0.152: R138.2 112.53,5.08 U4.3
N29979142: length 3
  BOTTOM w0.152: U4.5 112.24,6.38 R137.2
N29981843: length 1
  TOP w0.305: C36.1 85.72,34.16
N29981855: length 1
  TOP w0.305: C41.1 85.72,31.11
N29981879: length 2.5
  TOP w0.305: C36.2 R25.1 R21.1
N29981949: length 6.2
  TOP w0.508: T1.2 v1(108.33,30.43) T1.5
  BOTTOM w0.508: C39.2 v1(108.33,30.43)
N29981953: length 6.1
  TOP w0.508: T2.5 96.65,30.23 v1(96.65,30.23) 96.64,30.23 T2.2
  BOTTOM w0.508: C40.2 v1(96.65,30.23)
N29982125: length 6.9
  TOP w0.305: T2.6 99.87,32.77 100.76,31.88 R24.1 103.91,31.88 105,32.97 T1.4
N29982131: length 6.9
  TOP w0.305: T2.4 99.9,27.69 101.04,28.83 R26.2 104.06,28.83 105,27.89 T1.6
N29982143: length 8.5
  TOP w0.305: R20.2 86.74,33.38 87.81,32.31 93.37,32.31 T2.1
N29982145: length 8.5
  TOP w0.305: R30.2 87.66,30.2 87.66,30.2 90.17,27.69 T2.3
N29982157: length 2.5
  TOP w0.305: C41.2 R27.2 R32.1
N29982173: length 3
  TOP w0.305: T1.1 113.97,27.89 R31.1
N29999539: length 1
  TOP w0.305: 85.72,45.34 C42.1
N29999545: length 1
  TOP w0.305: 85.72,42.29 C47.1
N29999563: length 2.5
  TOP w0.305: C42.2 R38.1 R34.1
N29999622: length 6.1
  TOP w0.508: T3.2 v1(108.2,46.1) T3.5
  BOTTOM w0.508: C45.2 v1(108.2,46.1)
N29999634: length 6.1
  TOP w0.508: T4.2 v1(96.75,45.95) T4.5
  BOTTOM w0.508: C46.2 v1(96.75,45.95)
N29999775: length 6.7
  TOP w0.305: T4.6 100,48.49 100.99,47.5 R37.1 103.78,47.5 104.93,48.64 105.41,48.64
N29999779: length 6.6
  TOP w0.305: T4.4 100,43.41 101.04,44.45 R39.2 104.06,44.45 104.95,43.56 T3.6
N29999791: length 8.5
  TOP w0.305: T4.1 89.89,48.49 R33.2
N29999793: length 8.5
  TOP w0.305: T4.3 93.47,43.92 87.71,43.92 86.74,42.95 R43.2
N29999803: length 2.5
  TOP w0.305: R44.1 R40.2 C47.2
N29999817: length 2.9
  TOP w0.305: T3.1 R42.1
N30111387: length 2.7
  TOP w0.254: U8.2 130.56,80.26 129.92,79.63 128.4,79.63
N30111389: length 13.4
  TOP w0.254: U8.5 v1(130.56,81.66) ; U8.3 132.38,80.57 C137.1
  BOTTOM w0.508: v1(130.56,81.66) 130.56,81.15 131.39,80.31 v1(131.75,80.31) 134.16,80.31 135.36,81.51 138.28,81.51 JP20.2
N30111452: length 1.9
  TOP w0.254: L19.2 129.41,81.66 129.96,81.11 U8.6
N30111497: length 2.7
  BOTTOM w1.016: FB12.1 JP13.2
N30111569: length 13.3
  BOTTOM w0.762: U9.2 133.22,74.32 C140.1 134.19,74.17 134.49,74.47 U9.1 134.75,76.63 137.57,76.63 139.83,78.89 JP14.2
N30111571: length 1.6
  BOTTOM w0.508: C141.1 129.24,76.71 U9.5
N30111598: length 11.4
  BOTTOM w0.762: 130.68,76.89 130.68,75.67 130.58,75.56 C142.1 130.58,73.66 129.84,72.92 127.71,72.92 125.04,75.59 JP13.3
N30152047: length 2
  TOP w0.305: R28.1 C38.2 L1.2
N30152584: length 2
  TOP w0.305: 79.63,33.15 R23.2
N30155281: length 2
  TOP w0.305: R35.2 C44.1 L2.1
N30155822: length 2
  TOP w0.305: R41.1 C44.2 L2.2
N30525626: length 2.9
  TOP w0.305: R22.2 113.87,32.97 T1.3
N30527255: length 2.9
  TOP w0.305: 111,48.64 R36.2
N30929266: length 11.9
  TOP w0.305: R72.1 72,63.87 70.12,61.99 R144.1
N31014668: length 11
  TOP w0.508: v1(69.11,98.93) 68.81,99.24 68.81,99.94 U17.1 69.01,101.63 R164.2 R165.1 70.05,106.73 TP14.1
  BOTTOM w0.508: U16.8 69.88,98.17 v1(69.11,98.93)
N31014687: length 7.5
  TOP w0.305: C177.1 R157.1 71.58,89.36 74.68,92.46 75.85,92.46 U17.5
N31014712: length 3.3
  TOP w0.508: FB25.2 C180.1 79.4,106.65 JP17.1
N31036180: length 2.9
  BOTTOM w0.152: R158.2 112.16,4.43 U4.2
N31036604: length 3.1
  BOTTOM w0.152: R159.2 112.61,8.98 U4.9
N31037032: length 3
  BOTTOM w0.152: U4.10 112.24,9.63 R160.2
N31071827: length 1.7
  BOTTOM w0.508: R143.1 118.82,93.78 120.02,92.58
N31076049: length 2.7
  BOTTOM w1.016: JP12.2 122.61,89.03 FB9.1
N31079418: length 1.7
  BOTTOM w0.508: R145.1 122.28,82.98 FB12.3
N31166599: length 13.7
  TOP w0.305: R161.1 67.7,48.17 70.26,50.72 J19.1
N31236900: length 1.3
  BOTTOM w0.508: R131.1 121.95,98.68 122.68,98.68 C414.2
N31255553: length 3.3
  BOTTOM w1.016: FB15.3 114.17,88.04 JP18.1
N31355701: length 3.3
  TOP w0.305: U2.42 92.99,70.33 93.29,70.33 93.87,70.9 C83.1
N31356519: length 12.7
  TOP w0.305: J10.1 101.57,77.09 95.85,71.36 C83.2
N31627077: length 11.1
  TOP w0.508: T6.5 22.23,35.22 ; 22.23,35.22 T6.2 ; 22.23,35.22 22.21,35.2 17.99,35.2 17.99,35.2 C60.2
N31630401: length 4.2
  TOP w0.305: R94.1 24.34,38.41 T6.4
N31630404: length 4.2
  TOP w0.305: R95.1 19.93,38.22 T6.6
N31634141: length 24.8
  TOP w0.152: v1(6.75,50.48) 6.75,50.7 7.05,51 7.81,51 7.96,50.85 7.96,50.25 8.28,49.94 9.12,49.94 9.44,50.25 9.44,51.92 9.66,52.15 10.12,52.15 10.35,51.92 10.35,51.32 10.67,51 15.9,51 22.02,44.88 22.02,44.13 R93.2
  BOTTOM w0.152: v1(6.75,50.48) 6.73,50.5 6.02,50.5 6.01,50.51 5.29,50.51 J15.117
N31634154: length 25.1
  TOP w0.152: v1(6.22,50.98) 6.3,51.05 6.71,51.05 6.94,51.28 7.93,51.28 8.24,50.97 8.24,50.37 8.39,50.22 9,50.22 9.16,50.37 9.16,52.03 9.55,52.43 10.24,52.43 10.63,52.03 10.63,51.44 10.78,51.28 16.02,51.28 16.37,50.93 16.41,50.93 22.33,45.01 22.33,44.07 R64.2
  BOTTOM w0.152: v1(6.22,50.98) 6.04,50.8 5.88,50.8 5.87,50.79 5.27,50.79 J15.115
N31649883: length 1.8
  BOTTOM w0.508: Q1.3 123.51,108.64 U18.4
N294889280: length 8.8
  TOP w0.305: J11.1 107.93,72.13 C74.1
N294896140: length 1.5
  TOP w0.305: C52.2 93.09,88.7 R71.1
N296597010: length 33.3
  TOP w0.152: SW1.1 77.17,24.16 68.1,33.22 61.57,33.22 59.94,34.85 58.6,34.85 58.09,34.34 56.06,34.34 54.41,35.99 v1(54.36,35.99)
  BOTTOM w0.508: R2.1 54.02,36.33 v1(54.36,35.99)
N298553540: length 1
  BOTTOM w0.152: R15.1 R14.2
N310146821: length 4.6
  TOP w0.305: R157.2 v1(70.56,92.63)
  BOTTOM w0.305: v1(70.56,92.63) 70.56,93.45 U16.5

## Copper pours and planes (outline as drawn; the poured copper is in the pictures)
3.3V_CDC_CP on L3_PWR: 102.87,99.31 78.36,99.31 71.25,92.2 71.25,64.39 76.77,58.86 82.87,64.96 80.58,67.25 79.12,65.79 77.09,65.79 76.2,66.67 76.2,73.66 86.36,83.82 95.25,83.82 102.87,91.44
5V on BOTTOM (solid shape): 124.71,99.7 115.19,99.7 115.19,100.71 121.16,100.71 121.16,101.98 122.43,101.98 122.43,100.2 123.57,100.2 123.57,103.38 124.71,103.38
5V on L4_PWR: 137.79,76.84 126.49,76.84 126.49,90.93 112.4,90.93 112.4,109.22 137.79,109.22
+1.8V_CLK on TOP (solid shape): 49.25,13.97 46.33,13.97 46.33,15.75 49.25,15.75
+1.8V_CLK on L3_PWR: 59.05,48.9 59.05,13.08 47.37,13.08 47.37,29.34 50.04,32 50.04,41.91 49.28,42.67 49.28,48.9
+1.8VA_ADC on TOP (solid shape): 49.25,17.91 46.33,17.91 46.33,19.68 49.25,19.68
+1.8VA_ADC on BOTTOM (solid shape): 55.96,40.69 55.93,40.69 54.97,39.73 54.38,39.73 53.57,38.91 53.57,38.4 53.01,37.85 52.07,37.85 51.33,38.58 51.33,38.81 52.3,39.78 52.53,39.55 52.53,39.5 53.26,39.5 54.15,40.39 53.59,40.94 52.17,40.94 49.86,43.26 49.86,43.56 51.47,45.17
+1.8VA_ADC on L4_PWR: 58.42,45.09 58.42,17.78 46.99,17.78 46.99,28.57 50.16,31.75 50.16,43.56 51.69,45.09
+1.8VD on TOP (solid shape): 43.76,19.84 43.76,13.74 43,12.98 42.24,12.98 41.99,13.23 41.99,20.35 42.24,20.6 43,20.6
+1.8VD on BOTTOM (solid shape): 40.28,41.12 39.45,40.28 38.99,40.28 38.84,40.13 38.84,39.14 38.89,39.09 38.89,38.96 38.33,38.4 38.25,38.4 36.73,39.93 36.73,40.36 38.53,42.16 39.24,42.16
+1.8VD on BOTTOM (solid shape): 119.94,82.5 120.62,81.81 120.62,76.71 123.19,76.71 123.19,74.3 120.02,74.3 120.02,78.66 119.76,78.92 119.76,79.93 119.61,80.09 119.61,81.36 119.58,81.33 119.58,82.17 119.43,82.32 119.43,83.24 119.94,83.24
+1.8VD on L3_PWR: 45.72,30.61 45.72,13.08 36.2,13.08 36.2,44.83 42.04,44.83 42.55,44.32 43.81,44.32 43.81,45.21 43.43,45.59 43.43,46.74 44.32,46.74 48.26,42.8 48.26,33.15
+1.8VD on L4_PWR: 31.75,42.16 31.75,5.08 137.67,5.08 137.67,74.3 123.83,74.3 123.83,76.84 119.38,76.84 116.2,73.66 116.2,26.04 61.59,26.04 61.59,13.08 44.45,13.08 44.45,29.21 48.26,33.02 48.26,35.94 42.04,42.16
+3.3V_CLK on L3_PWR: 41.91,109.22 41.91,52.07 93.98,52.07 103.51,61.59 115.44,61.59 115.44,72.39 111.76,72.39 111.76,90.81 105.41,90.81 95.89,81.28 87,81.28 77.6,71.88 77.6,67.31 78.3,66.61 80.14,68.45 80.9,68.45 84.52,64.83 76.83,57.15 69.85,64.14 69.85,85.22 70.36,85.73 70.36,93.47 77.85,100.97 102.87,100.97 102.87,109.22
+3.3VA_DAC on BOTTOM (solid shape): 49.35,47.12 49.35,45.69 48.39,44.73 46.79,46.33 45.57,46.33 45.39,46.18 45.14,46.48 45.14,46.99 44.12,48.01 44.12,48.36 45.49,49.73 46.74,49.73
+3.3VA_DAC on BOTTOM (solid shape): 118.01,92.94 118.11,92.84 118.11,87.76 118.36,87.5 118.36,82.93 114.68,82.93 114.68,84.71 117.22,84.71 117.22,87.5 117.6,87.88 117.6,90.04 117.35,90.3 117.35,91.31 117.09,91.57 117.09,92.84 117.22,92.96 117.22,94.06 118.01,94.06
+3.3VA_DAC on L4_PWR: 29.21,76.2 29.21,47.12 29.33,45.09 42.16,45.09 42.67,44.58 43.56,44.58 43.56,45.21 43.18,45.59 43.18,47.5 44.45,47.5 47.24,44.7 49.02,44.7 51.94,47.62 73.03,47.62 73.03,75.56 113.67,75.56 121.92,83.82 121.92,88.27 57.15,88.27 53.98,85.09 53.98,68.58 55.25,67.31 55.25,57.02 39.37,57.02 39.37,66.04 40.77,67.44 40.77,76.2
+5VA on L4_PWR: 111.12,90.81 111.12,94.62 109.86,94.62 109.86,109.22 31.75,109.22 31.75,78.74 43.18,78.74 43.18,66.04 41.91,64.77 41.91,59.31 52.7,59.31 52.7,66.67 52.07,67.31 52.07,87 55.88,90.81
+6.0VDC on BOTTOM (solid shape): 120.14,103.25 115.32,103.25 115.32,106.3 120.14,106.3
+6.0VDC on BOTTOM (solid shape): 114.68,107.82 113.41,107.82 113.41,109.86 111.63,109.86 111.63,108.97 109.22,108.97 109.22,110.74 114.68,110.74
+6.0VDC on L3_PWR: 105.41,111.12 113.67,111.12 113.67,106.3 119.63,106.3 124.33,101.6 137.79,101.6 137.79,77.47 114.3,77.47 114.3,93.34 105.41,93.34
GND on TOP: 26.92,0.25 26.92,11.68 3.94,11.68 0.25,15.37 0.25,98.93 3.94,102.62 26.92,102.62 26.92,114.05 46.36,114.05 46.36,111.51 48.18,111.51 48.18,114.05 141.99,114.05 141.99,57.45 139.85,57.45 139.85,55.63 141.99,55.63 141.99,47.29 138.99,47.29 138.99,45.47 141.99,45.47 141.99,37.13 138.84,37.13 138.84,35.31 141.99,35.31 141.99,26.97 139.67,26.97 139.67,25.15 141.99,25.15 141.99,0.25
GND on BOTTOM: 26.92,0.38 26.92,11.68 3.94,11.68 0.25,15.37 0.25,98.93 3.94,102.62 26.92,102.62 26.92,113.92 141.99,113.92 141.99,0.38
GND on L2_GND, L5_GND: 26.92,0.38 26.92,11.68 3.94,11.68 0.25,15.37 0.25,98.93 3.94,102.62 26.92,102.62 26.92,113.92 141.86,113.92 141.86,0.38
GND on L3_PWR: 26.92,0.25 26.92,11.68 3.94,11.68 0.25,15.37 0.25,99.06 3.81,102.62 26.92,102.62 26.92,114.05 141.99,114.05 141.99,0.25 ; 1 cut-out
GND on L4_PWR: 26.92,0.25 26.92,11.68 3.94,11.68 0.25,15.37 0.25,98.93 3.94,102.62 26.92,102.62 26.92,114.05 141.99,114.05 141.99,0.25 ; 1 cut-out
GND on L4_PWR: 115.44,26.8 115.44,74.8 73.79,74.8 73.79,46.86 59.18,46.86 59.18,26.8
DACCLK_IN on TOP (solid shape): 23.88,34.42 23.88,33.79 24.14,33.53 25.38,33.53 25.38,31.78 24.16,31.78 24.16,32.49 23.17,33.48 23.17,34.42
IOUT-P-A on TOP (solid shape): 59.03,76.29 57.79,76.29 57.53,76.04 57.53,75.4 56.82,75.4 56.82,76.34 57.81,77.34 57.81,78.02 57.84,78.05 59.03,78.05
IOUT-P-B on TOP (solid shape): 41.61,76.12 40.36,76.12 40.11,75.86 40.11,75.23 39.4,75.23 39.4,76.17 40.39,77.16 40.39,77.84 40.41,77.87 41.61,77.87
IOUTN-A on TOP (solid shape): 54.94,72.94 53.98,71.98 53.98,71.21 52.71,71.21 52.71,72.66 52.73,72.69 52.73,72.99 53.98,72.99 54.23,73.25 54.23,73.88 54.94,73.88
IOUTN-B on TOP (solid shape): 37.52,72.76 36.55,71.8 36.55,71.04 35.28,71.04 35.28,72.48 35.31,72.51 35.31,72.81 36.55,72.81 36.81,73.07 36.81,73.7 37.52,73.7
IOUTP-A on TOP (solid shape): 57.53,73.25 57.79,72.99 59.03,72.99 59.03,71.21 57.79,71.21 57.79,71.98 56.82,72.94 56.82,73.88 57.53,73.88
IOUTP-B on TOP (solid shape): 40.11,73.07 40.36,72.81 41.61,72.81 41.61,71.04 40.36,71.04 40.36,71.8 39.4,72.76 39.4,73.7 40.11,73.7
Net_341 on TOP (solid shape): 56.26,77.59 56.52,77.59 56.52,76.55 56.26,76.29 56.26,75.4 55.5,75.4 55.5,76.29 55.25,76.55 55.25,77.46 55.27,77.49 55.5,77.49 55.5,78.07 56.26,78.07
Net_342 on TOP (solid shape): 38.84,77.41 39.09,77.41 39.09,76.37 38.84,76.12 38.84,75.23 38.08,75.23 38.08,76.12 37.82,76.37 37.82,77.28 37.85,77.31 38.08,77.31 38.08,77.89 38.84,77.89
TCXO_VCC on TOP (solid shape): 79.63,101.85 80.14,101.35 80.14,97.66 79.63,97.66 79.63,99.19 78.87,99.95 75.44,99.95 75.44,101.47 78.61,101.47 79.12,101.98 79.12,102.62 79.63,102.62
N27836198 on TOP: 116.46,109.35 116.46,107.06 122.3,107.06 123.7,108.46 123.7,110.74 122.68,110.74 121.29,109.35
N27836198 on BOTTOM: 116.46,109.35 116.46,107.06 122.3,107.06 122.3,108.59 123.06,109.35 123.7,109.35 123.7,110.74 122.68,110.74 121.29,109.35
N27836198 on L3_PWR: 115.44,111.12 115.44,107.31 120.02,107.31 123.83,103.5 137.16,103.5 137.16,111.12
N27836250 on BOTTOM (solid shape): 130.43,111.51 130.43,109.86 128.52,107.95 128.52,105.03 130.94,102.62 130.94,100.33 129.67,99.06 127.38,99.06 125.98,100.46 125.98,102.87 126.37,103.25 126.37,106.17 125.22,106.17 124.21,107.19 124.21,112.39 129.54,112.39
N27836250 on TOP: 125.35,108.59 125.35,112.14 130.3,112.14 130.3,108.59
N28104733 on TOP (solid shape): 125.86,91.44 126.49,91.44 126.49,90.93 128.52,90.93 128.52,91.44 129.41,91.44 129.41,91.31 130.56,91.31 130.17,90.93 129.54,90.93 129.41,90.81 129.41,88.01 128.4,88.01 128.4,90.17 128.33,90.23 125.41,90.23 124.9,90.74 121.98,90.74 121.92,90.81 121.92,92.33 124.97,92.33
N29488937 on TOP (solid shape): 64.98,54.28 63.74,53.04 63.49,53.29 62.86,53.92 62.51,53.92 62.06,53.47 61.55,53.98 62.22,54.64 63.62,54.64 64.1,55.13 64.14,55.13
N29488984 on TOP (solid shape): 61.39,57.87 60.89,57.37 60.89,55.97 60.22,55.31 59.72,55.81 60.17,56.26 60.17,56.62 59.29,57.5 59.83,58.04 60.53,58.74
N29489396 on TOP (solid shape): 60.08,53.29 59.63,52.84 59.45,52.67 59.45,52.31 59.33,52.18 59.15,52.36 58.2,51.41 57.66,51.95 58.61,52.9 58.43,53.08 58.55,53.2 58.91,53.2 59.09,53.38 59.54,53.83
N29489396 on TOP (solid shape): 63.04,56.26 62.7,55.92 62.88,55.74 62.15,55 61.79,55 61.61,54.82 61.16,54.37 60.62,54.91 61.07,55.36 61.25,55.54 61.25,55.9 61.27,55.92 61.89,56.54 61.93,56.54 62.09,56.38 62.51,56.8
N29489542 on TOP (solid shape): 60.98,52.4 60.53,51.95 60.53,51.59 61.41,50.71 60.15,49.45 59.27,50.33 59.81,50.87 59.81,52.23 60.48,52.9
N29490446 on TOP (solid shape): 57.84,54.28 58.2,54.28 58.64,54.73 59.15,54.23 59.06,54.14 58.48,53.56 57.12,53.56 56.6,53.04 56.58,53.02 55.68,53.92 56.7,54.95 56.74,54.95 56.96,55.16
N29813928 on TOP (solid shape): 38.84,72.81 39.09,72.56 39.09,72.38 38.84,72.38 38.84,71.04 38.08,71.04 38.08,72.38 37.82,72.38 37.82,72.56 38.08,72.81 38.08,73.7 38.84,73.7
N29814197 on TOP (solid shape): 56.26,72.99 56.52,72.74 56.52,72.56 56.26,72.56 56.26,71.21 55.5,71.21 55.5,72.56 55.25,72.56 55.25,72.74 55.5,72.99 55.5,73.88 56.26,73.88
N29981949 on TOP (solid shape): 106.6,30.81 107.49,30.81 107.49,30.05 106.6,30.05 106.35,29.79 106.17,29.79 106.17,30.05 104.83,30.05 104.83,30.81 106.17,30.81 106.17,31.06 106.35,31.06
N29981949 on TOP (solid shape): 111.1,31.04 111.1,30.81 111.68,30.81 111.68,30.05 111.2,30.05 111.2,29.79 110.16,29.79 109.91,30.05 109.02,30.05 109.02,30.81 109.91,30.81 110.16,31.06 111.07,31.06
N29981953 on TOP (solid shape): 98.71,30.61 100.05,30.61 100.05,29.85 98.71,29.85 98.71,29.6 98.53,29.6 98.28,29.85 97.39,29.85 97.39,30.61 98.28,30.61 98.53,30.87 98.71,30.87
N29981953 on TOP (solid shape): 94.97,30.61 95.86,30.61 95.86,29.85 94.97,29.85 94.72,29.6 93.81,29.6 93.78,29.62 93.78,29.85 93.2,29.85 93.2,30.61 93.68,30.61 93.68,30.87 94.72,30.87
N29982125 on TOP (solid shape): 100.05,32.14 99.29,32.14 98.33,31.17 97.39,31.17 97.39,31.88 98.02,31.88 98.28,32.14 98.28,33.38 100.05,33.38
N29982125 on TOP (solid shape): 106.3,33.58 106.6,33.58 106.6,32.33 106.86,32.08 107.49,32.08 107.49,31.37 106.55,31.37 105.59,32.33 104.83,32.33 104.83,33.6 106.27,33.6
N29982131 on TOP (solid shape): 107.49,28.78 106.86,28.78 106.6,28.52 106.6,27.28 104.83,27.28 104.83,28.52 105.59,28.52 106.55,29.49 107.49,29.49
N29982131 on TOP (solid shape): 99.29,28.33 100.05,28.33 100.05,27.06 98.61,27.06 98.58,27.08 98.28,27.08 98.28,28.33 98.02,28.58 97.39,28.58 97.39,29.29 98.33,29.29
N29982143 on TOP (solid shape): 94.97,32.14 95.23,31.88 95.86,31.88 95.86,31.17 94.92,31.17 93.93,32.16 93.25,32.16 93.22,32.19 93.22,33.38 94.97,33.38
N29982145 on TOP (solid shape): 95.86,28.58 95.23,28.58 94.97,28.33 94.97,27.08 93.22,27.08 93.22,28.3 93.93,28.3 94.92,29.29 95.86,29.29
N29982173 on TOP (solid shape): 110.95,28.5 111.63,28.5 111.66,28.47 111.66,27.28 109.91,27.28 109.91,28.52 109.65,28.78 109.02,28.78 109.02,29.49 109.96,29.49
N29999622 on TOP (solid shape): 106.55,46.48 107.44,46.48 107.44,45.72 106.55,45.72 106.3,45.47 106.12,45.47 106.12,45.72 104.78,45.72 104.78,46.48 106.12,46.48 106.12,46.74 106.3,46.74
N29999622 on TOP (solid shape): 111.05,46.71 111.05,46.48 111.63,46.48 111.63,45.72 111.15,45.72 111.15,45.47 110.11,45.47 109.86,45.72 108.97,45.72 108.97,46.48 109.86,46.48 110.11,46.74 111.02,46.74
N29999634 on TOP (solid shape): 98.86,46.33 100.2,46.33 100.2,45.57 98.86,45.57 98.86,45.31 98.68,45.31 98.42,45.57 97.54,45.57 97.54,46.33 98.42,46.33 98.68,46.58 98.86,46.58
N29999634 on TOP (solid shape): 95.12,46.33 96.01,46.33 96.01,45.57 95.12,45.57 94.87,45.31 93.95,45.31 93.93,45.34 93.93,45.57 93.34,45.57 93.34,46.33 93.83,46.33 93.83,46.58 94.87,46.58
N29999775 on TOP (solid shape): 100.2,47.85 99.44,47.85 98.48,46.89 97.54,46.89 97.54,47.6 98.17,47.6 98.42,47.85 98.42,49.1 100.2,49.1
N29999775 on TOP (solid shape): 106.25,49.25 106.55,49.25 106.55,48.01 106.81,47.75 107.44,47.75 107.44,47.04 106.5,47.04 105.54,48.01 104.78,48.01 104.78,49.28 106.22,49.28
N29999779 on TOP (solid shape): 107.44,44.45 106.81,44.45 106.55,44.2 106.55,42.95 104.78,42.95 104.78,44.2 105.54,44.2 106.5,45.16 107.44,45.16
